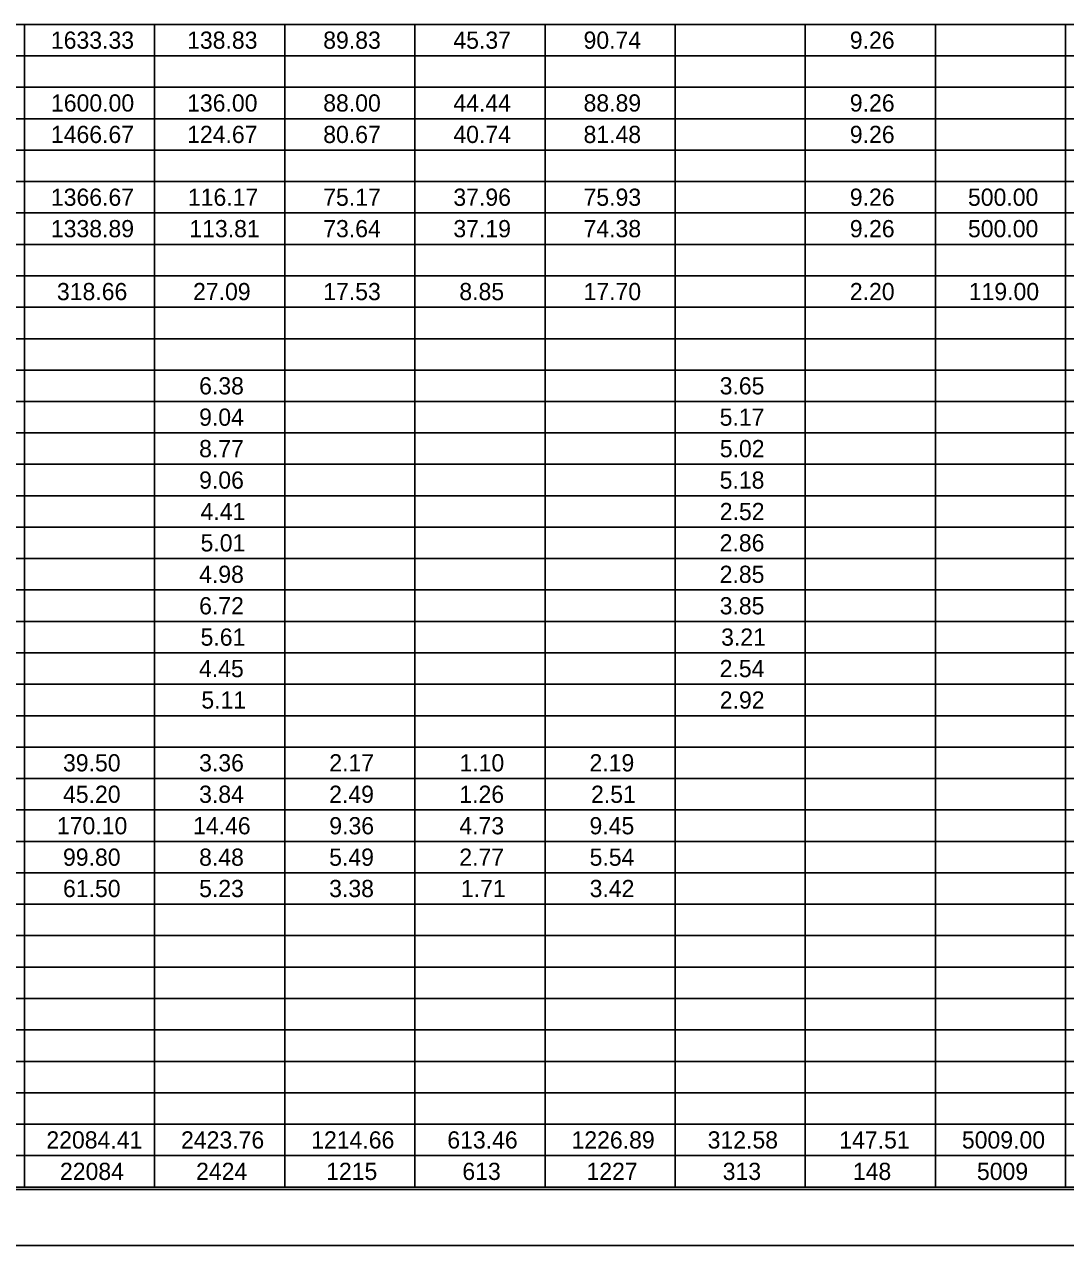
# Model space of a CAD drawing. Extents: x 0 to 34, y 0 to 22.
# Drawn here: x 16.38 to 25.65, y 0 to 10.87 of the extents above; entities that cross this region are included whole.
import ezdxf

# ---------------------------------------------------------------- set-up
doc = ezdxf.new("R2010")
doc.units = 0
for name, color, linetype in [('SH_Border', 7, 'Continuous'), ('SH_Cut_Line', 7, 'Continuous'), ('SH_Text', 7, 'Continuous')]:
    doc.layers.add(name, color=color, linetype=linetype)

msp = doc.modelspace()

# ---------------------------------------------------------------- linework, layer by layer
at = {"layer": 'SH_Border'}
msp.add_lwpolyline([(1.5, 21.5), (33.5, 21.5), (33.5, 0.5), (1.5, 0.5)], close=True, dxfattribs=at)
at = {"layer": 'SH_Cut_Line'}
msp.add_lwpolyline([(0, 0), (34, 0), (34, 22), (0, 22)], close=True, dxfattribs=at)
at = {"layer": 'SH_Text'}
for p, q in [((15.22, 10.871), (16.378, 10.871)), ((16.378, 10.871), (24.49, 10.871)), ((16.378, 10.871), (16.378, 10.591)), ((17.537, 10.871), (17.537, 10.591)), ((18.696, 10.871), (18.696, 10.591)), ((19.855, 10.871), (19.855, 10.591)), ((21.014, 10.871), (21.014, 10.591)), ((22.173, 10.871), (22.173, 10.591)), ((23.331, 10.871), (23.331, 10.591)), ((24.49, 10.871), (25.649, 10.871)), ((24.49, 10.871), (24.49, 10.591)), ((25.649, 10.871), (27.967, 10.871)), ((25.649, 10.871), (25.649, 10.591)), ((15.22, 10.591), (16.378, 10.591)), ((16.378, 10.591), (24.49, 10.591)), ((16.378, 10.591), (16.378, 10.311)), ((17.537, 10.591), (17.537, 10.311)), ((18.696, 10.591), (18.696, 10.311)), ((19.855, 10.591), (19.855, 10.311)), ((21.014, 10.591), (21.014, 10.311)), ((22.173, 10.591), (22.173, 10.311)), ((23.331, 10.591), (23.331, 10.311)), ((24.49, 10.591), (25.649, 10.591)), ((24.49, 10.591), (24.49, 10.311)), ((25.649, 10.591), (27.967, 10.591)), ((25.649, 10.591), (25.649, 10.311)), ((15.22, 10.311), (16.378, 10.311)), ((16.378, 10.311), (24.49, 10.311)), ((16.378, 10.311), (16.378, 10.031)), ((17.537, 10.311), (17.537, 10.031)), ((18.696, 10.311), (18.696, 10.031)), ((19.855, 10.311), (19.855, 10.031)), ((21.014, 10.311), (21.014, 10.031)), ((22.173, 10.311), (22.173, 10.031)), ((23.331, 10.311), (23.331, 10.031)), ((24.49, 10.311), (25.649, 10.311)), ((24.49, 10.311), (24.49, 10.031)), ((25.649, 10.311), (27.967, 10.311)), ((25.649, 10.311), (25.649, 10.031)), ((15.22, 10.031), (16.378, 10.031)), ((16.378, 10.031), (24.49, 10.031)), ((16.378, 10.031), (16.378, 9.752)), ((17.537, 10.031), (17.537, 9.752)), ((18.696, 10.031), (18.696, 9.752)), ((19.855, 10.031), (19.855, 9.752)), ((21.014, 10.031), (21.014, 9.752)), ((22.173, 10.031), (22.173, 9.752)), ((23.331, 10.031), (23.331, 9.752)), ((24.49, 10.031), (25.649, 10.031)), ((24.49, 10.031), (24.49, 9.752)), ((25.649, 10.031), (27.967, 10.031)), ((25.649, 10.031), (25.649, 9.752)), ((15.22, 9.752), (16.378, 9.752)), ((16.378, 9.752), (24.49, 9.752)), ((16.378, 9.752), (16.378, 9.472)), ((17.537, 9.752), (17.537, 9.472)), ((18.696, 9.752), (18.696, 9.472)), ((19.855, 9.752), (19.855, 9.472)), ((21.014, 9.752), (21.014, 9.472)), ((22.173, 9.752), (22.173, 9.472)), ((23.331, 9.752), (23.331, 9.472)), ((24.49, 9.752), (25.649, 9.752)), ((24.49, 9.752), (24.49, 9.472)), ((25.649, 9.752), (27.967, 9.752)), ((25.649, 9.752), (25.649, 9.472)), ((15.22, 9.472), (16.378, 9.472)), ((16.378, 9.472), (24.49, 9.472)), ((16.378, 9.472), (16.378, 9.192)), ((17.537, 9.472), (17.537, 9.192)), ((18.696, 9.472), (18.696, 9.192)), ((19.855, 9.472), (19.855, 9.192)), ((21.014, 9.472), (21.014, 9.192)), ((22.173, 9.472), (22.173, 9.192)), ((23.331, 9.472), (23.331, 9.192)), ((24.49, 9.472), (25.649, 9.472)), ((24.49, 9.472), (24.49, 9.192)), ((25.649, 9.472), (27.967, 9.472)), ((25.649, 9.472), (25.649, 9.192)), ((15.22, 9.192), (16.378, 9.192)), ((16.378, 9.192), (24.49, 9.192)), ((16.378, 9.192), (16.378, 8.913)), ((17.537, 9.192), (17.537, 8.913)), ((18.696, 9.192), (18.696, 8.913)), ((19.855, 9.192), (19.855, 8.913)), ((21.014, 9.192), (21.014, 8.913)), ((22.173, 9.192), (22.173, 8.913)), ((23.331, 9.192), (23.331, 8.913)), ((24.49, 9.192), (25.649, 9.192)), ((24.49, 9.192), (24.49, 8.913)), ((25.649, 9.192), (27.967, 9.192)), ((25.649, 9.192), (25.649, 8.913)), ((15.22, 8.913), (16.378, 8.913)), ((16.378, 8.913), (24.49, 8.913)), ((16.378, 8.913), (16.378, 8.633)), ((17.537, 8.913), (17.537, 8.633)), ((18.696, 8.913), (18.696, 8.633)), ((19.855, 8.913), (19.855, 8.633)), ((21.014, 8.913), (21.014, 8.633)), ((22.173, 8.913), (22.173, 8.633)), ((23.331, 8.913), (23.331, 8.633)), ((24.49, 8.913), (25.649, 8.913)), ((24.49, 8.913), (24.49, 8.633)), ((25.649, 8.913), (27.967, 8.913)), ((25.649, 8.913), (25.649, 8.633)), ((15.22, 8.633), (16.378, 8.633)), ((16.378, 8.633), (24.49, 8.633)), ((16.378, 8.633), (16.378, 8.353)), ((17.537, 8.633), (17.537, 8.353)), ((18.696, 8.633), (18.696, 8.353)), ((19.855, 8.633), (19.855, 8.353)), ((21.014, 8.633), (21.014, 8.353)), ((22.173, 8.633), (22.173, 8.353)), ((23.331, 8.633), (23.331, 8.353)), ((24.49, 8.633), (25.649, 8.633)), ((24.49, 8.633), (24.49, 8.353)), ((25.649, 8.633), (27.967, 8.633)), ((25.649, 8.633), (25.649, 8.353)), ((15.22, 8.353), (16.378, 8.353)), ((16.378, 8.353), (24.49, 8.353)), ((16.378, 8.353), (16.378, 8.073)), ((17.537, 8.353), (17.537, 8.073)), ((18.696, 8.353), (18.696, 8.073)), ((19.855, 8.353), (19.855, 8.073)), ((21.014, 8.353), (21.014, 8.073)), ((22.173, 8.353), (22.173, 8.073)), ((23.331, 8.353), (23.331, 8.073)), ((24.49, 8.353), (25.649, 8.353)), ((24.49, 8.353), (24.49, 8.073)), ((25.649, 8.353), (27.967, 8.353)), ((25.649, 8.353), (25.649, 8.073)), ((15.22, 8.073), (16.378, 8.073)), ((16.378, 8.073), (24.49, 8.073)), ((16.378, 8.073), (16.378, 7.794)), ((17.537, 8.073), (17.537, 7.794)), ((18.696, 8.073), (18.696, 7.794)), ((19.855, 8.073), (19.855, 7.794)), ((21.014, 8.073), (21.014, 7.794)), ((22.173, 8.073), (22.173, 7.794)), ((23.331, 8.073), (23.331, 7.794)), ((24.49, 8.073), (25.649, 8.073)), ((24.49, 8.073), (24.49, 7.794)), ((25.649, 8.073), (27.967, 8.073)), ((25.649, 8.073), (25.649, 7.794)), ((15.22, 7.794), (16.378, 7.794)), ((16.378, 7.794), (24.49, 7.794)), ((16.378, 7.794), (16.378, 7.514)), ((17.537, 7.794), (17.537, 7.514)), ((18.696, 7.794), (18.696, 7.514)), ((19.855, 7.794), (19.855, 7.514)), ((21.014, 7.794), (21.014, 7.514)), ((22.173, 7.794), (22.173, 7.514)), ((23.331, 7.794), (23.331, 7.514)), ((24.49, 7.794), (25.649, 7.794)), ((24.49, 7.794), (24.49, 7.514)), ((25.649, 7.794), (27.967, 7.794)), ((25.649, 7.794), (25.649, 7.514)), ((15.22, 7.514), (16.378, 7.514)), ((16.378, 7.514), (24.49, 7.514)), ((16.378, 7.514), (16.378, 7.234)), ((17.537, 7.514), (17.537, 7.234)), ((18.696, 7.514), (18.696, 7.234)), ((19.855, 7.514), (19.855, 7.234)), ((21.014, 7.514), (21.014, 7.234)), ((22.173, 7.514), (22.173, 7.234)), ((23.331, 7.514), (23.331, 7.234)), ((24.49, 7.514), (25.649, 7.514)), ((24.49, 7.514), (24.49, 7.234)), ((25.649, 7.514), (27.967, 7.514)), ((25.649, 7.514), (25.649, 7.234)), ((15.22, 7.234), (16.378, 7.234)), ((16.378, 7.234), (24.49, 7.234)), ((16.378, 7.234), (16.378, 6.955)), ((17.537, 7.234), (17.537, 6.955)), ((18.696, 7.234), (18.696, 6.955)), ((19.855, 7.234), (19.855, 6.955)), ((21.014, 7.234), (21.014, 6.955)), ((22.173, 7.234), (22.173, 6.955)), ((23.331, 7.234), (23.331, 6.955)), ((24.49, 7.234), (25.649, 7.234)), ((24.49, 7.234), (24.49, 6.955)), ((25.649, 7.234), (27.967, 7.234)), ((25.649, 7.234), (25.649, 6.955)), ((15.22, 6.955), (16.378, 6.955)), ((16.378, 6.955), (24.49, 6.955)), ((16.378, 6.955), (16.378, 6.675)), ((17.537, 6.955), (17.537, 6.675)), ((18.696, 6.955), (18.696, 6.675)), ((19.855, 6.955), (19.855, 6.675)), ((21.014, 6.955), (21.014, 6.675)), ((22.173, 6.955), (22.173, 6.675)), ((23.331, 6.955), (23.331, 6.675)), ((24.49, 6.955), (25.649, 6.955)), ((24.49, 6.955), (24.49, 6.675)), ((25.649, 6.955), (27.967, 6.955)), ((25.649, 6.955), (25.649, 6.675)), ((15.22, 6.675), (16.378, 6.675)), ((16.378, 6.675), (24.49, 6.675)), ((16.378, 6.675), (16.378, 6.395)), ((17.537, 6.675), (17.537, 6.395)), ((18.696, 6.675), (18.696, 6.395)), ((19.855, 6.675), (19.855, 6.395)), ((21.014, 6.675), (21.014, 6.395)), ((22.173, 6.675), (22.173, 6.395)), ((23.331, 6.675), (23.331, 6.395)), ((24.49, 6.675), (25.649, 6.675)), ((24.49, 6.675), (24.49, 6.395)), ((25.649, 6.675), (27.967, 6.675)), ((25.649, 6.675), (25.649, 6.395)), ((15.22, 6.395), (16.378, 6.395)), ((16.378, 6.395), (24.49, 6.395)), ((16.378, 6.395), (16.378, 6.115)), ((17.537, 6.395), (17.537, 6.115)), ((18.696, 6.395), (18.696, 6.115)), ((19.855, 6.395), (19.855, 6.115)), ((21.014, 6.395), (21.014, 6.115)), ((22.173, 6.395), (22.173, 6.115)), ((23.331, 6.395), (23.331, 6.115)), ((24.49, 6.395), (25.649, 6.395)), ((24.49, 6.395), (24.49, 6.115)), ((25.649, 6.395), (27.967, 6.395)), ((25.649, 6.395), (25.649, 6.115)), ((15.22, 6.115), (16.378, 6.115)), ((16.378, 6.115), (24.49, 6.115)), ((16.378, 6.115), (16.378, 5.836)), ((17.537, 6.115), (17.537, 5.836)), ((18.696, 6.115), (18.696, 5.836)), ((19.855, 6.115), (19.855, 5.836)), ((21.014, 6.115), (21.014, 5.836)), ((22.173, 6.115), (22.173, 5.836)), ((23.331, 6.115), (23.331, 5.836)), ((24.49, 6.115), (25.649, 6.115)), ((24.49, 6.115), (24.49, 5.836)), ((25.649, 6.115), (27.967, 6.115)), ((25.649, 6.115), (25.649, 5.836)), ((15.22, 5.836), (16.378, 5.836)), ((16.378, 5.836), (24.49, 5.836)), ((16.378, 5.836), (16.378, 5.276)), ((17.537, 5.836), (17.537, 5.276)), ((18.696, 5.836), (18.696, 5.276)), ((19.855, 5.836), (19.855, 5.276)), ((21.014, 5.836), (21.014, 5.276)), ((22.173, 5.836), (22.173, 5.276)), ((23.331, 5.836), (23.331, 5.276)), ((24.49, 5.836), (25.649, 5.836)), ((24.49, 5.836), (24.49, 5.276)), ((25.649, 5.836), (27.967, 5.836)), ((25.649, 5.836), (25.649, 5.276)), ((15.22, 5.556), (16.378, 5.556)), ((16.378, 5.556), (24.49, 5.556)), ((24.49, 5.556), (25.649, 5.556)), ((25.649, 5.556), (27.967, 5.556)), ((15.22, 5.276), (16.378, 5.276)), ((16.378, 5.276), (24.49, 5.276)), ((16.378, 5.276), (16.378, 4.997)), ((17.537, 5.276), (17.537, 4.997)), ((18.696, 5.276), (18.696, 4.997)), ((19.855, 5.276), (19.855, 4.997)), ((21.014, 5.276), (21.014, 4.997)), ((22.173, 5.276), (22.173, 4.997)), ((23.331, 5.276), (23.331, 4.997)), ((24.49, 5.276), (25.649, 5.276)), ((24.49, 5.276), (24.49, 4.997)), ((25.649, 5.276), (27.967, 5.276)), ((25.649, 5.276), (25.649, 4.997)), ((15.22, 4.997), (16.378, 4.997)), ((16.378, 4.997), (24.49, 4.997)), ((16.378, 4.997), (16.378, 4.717)), ((17.537, 4.997), (17.537, 4.717)), ((18.696, 4.997), (18.696, 4.717)), ((19.855, 4.997), (19.855, 4.717)), ((21.014, 4.997), (21.014, 4.717)), ((22.173, 4.997), (22.173, 4.717)), ((23.331, 4.997), (23.331, 4.717)), ((24.49, 4.997), (25.649, 4.997)), ((24.49, 4.997), (24.49, 4.717)), ((25.649, 4.997), (27.967, 4.997)), ((25.649, 4.997), (25.649, 4.717)), ((15.22, 4.717), (16.378, 4.717)), ((16.378, 4.717), (24.49, 4.717)), ((16.378, 4.717), (16.378, 4.437)), ((17.537, 4.717), (17.537, 4.437)), ((18.696, 4.717), (18.696, 4.437)), ((19.855, 4.717), (19.855, 4.437)), ((21.014, 4.717), (21.014, 4.437)), ((22.173, 4.717), (22.173, 4.437)), ((23.331, 4.717), (23.331, 4.437)), ((24.49, 4.717), (25.649, 4.717)), ((24.49, 4.717), (24.49, 4.437)), ((25.649, 4.717), (27.967, 4.717)), ((25.649, 4.717), (25.649, 4.437)), ((15.22, 4.437), (16.378, 4.437)), ((16.378, 4.437), (24.49, 4.437)), ((16.378, 4.437), (16.378, 3.878)), ((17.537, 4.437), (17.537, 3.878)), ((18.696, 4.437), (18.696, 3.878)), ((19.855, 4.437), (19.855, 3.878)), ((21.014, 4.437), (21.014, 3.878)), ((22.173, 4.437), (22.173, 3.878)), ((23.331, 4.437), (23.331, 3.878)), ((24.49, 4.437), (25.649, 4.437)), ((24.49, 4.437), (24.49, 3.878)), ((25.649, 4.437), (27.967, 4.437)), ((25.649, 4.437), (25.649, 3.878)), ((15.22, 4.157), (16.378, 4.157)), ((16.378, 4.157), (24.49, 4.157)), ((24.49, 4.157), (25.649, 4.157)), ((25.649, 4.157), (27.967, 4.157)), ((15.22, 3.878), (16.378, 3.878)), ((16.378, 3.878), (24.49, 3.878)), ((16.378, 3.878), (16.378, 3.598)), ((17.537, 3.878), (17.537, 3.598)), ((18.696, 3.878), (18.696, 3.598)), ((19.855, 3.878), (19.855, 3.598)), ((21.014, 3.878), (21.014, 3.598)), ((22.173, 3.878), (22.173, 3.598)), ((23.331, 3.878), (23.331, 3.598)), ((24.49, 3.878), (25.649, 3.878)), ((24.49, 3.878), (24.49, 3.598)), ((25.649, 3.878), (27.967, 3.878)), ((25.649, 3.878), (25.649, 3.598)), ((15.22, 3.598), (16.378, 3.598)), ((16.378, 3.598), (24.49, 3.598)), ((16.378, 3.598), (16.378, 3.318)), ((17.537, 3.598), (17.537, 3.318)), ((18.696, 3.598), (18.696, 3.318)), ((19.855, 3.598), (19.855, 3.318)), ((21.014, 3.598), (21.014, 3.318)), ((22.173, 3.598), (22.173, 3.318)), ((23.331, 3.598), (23.331, 3.318)), ((24.49, 3.598), (25.649, 3.598)), ((24.49, 3.598), (24.49, 3.318)), ((25.649, 3.598), (27.967, 3.598)), ((25.649, 3.598), (25.649, 3.318)), ((15.22, 3.318), (16.378, 3.318)), ((16.378, 3.318), (24.49, 3.318)), ((16.378, 3.318), (16.378, 3.038)), ((17.537, 3.318), (17.537, 3.038)), ((18.696, 3.318), (18.696, 3.038)), ((19.855, 3.318), (19.855, 3.038)), ((21.014, 3.318), (21.014, 3.038)), ((22.173, 3.318), (22.173, 3.038)), ((23.331, 3.318), (23.331, 3.038)), ((24.49, 3.318), (25.649, 3.318)), ((24.49, 3.318), (24.49, 3.038)), ((25.649, 3.318), (27.967, 3.318)), ((25.649, 3.318), (25.649, 3.038)), ((15.22, 3.038), (16.378, 3.038)), ((16.378, 3.038), (24.49, 3.038)), ((16.378, 3.038), (16.378, 2.479)), ((17.537, 3.038), (17.537, 2.479)), ((18.696, 3.038), (18.696, 2.479)), ((19.855, 3.038), (19.855, 2.479)), ((21.014, 3.038), (21.014, 2.479)), ((22.173, 3.038), (22.173, 2.479)), ((23.331, 3.038), (23.331, 2.479)), ((24.49, 3.038), (25.649, 3.038)), ((24.49, 3.038), (24.49, 2.479)), ((25.649, 3.038), (27.967, 3.038)), ((25.649, 3.038), (25.649, 2.479)), ((15.22, 2.759), (16.378, 2.759)), ((16.378, 2.759), (24.49, 2.759)), ((24.49, 2.759), (25.649, 2.759)), ((25.649, 2.759), (27.967, 2.759)), ((15.22, 2.479), (16.378, 2.479)), ((16.378, 2.479), (24.49, 2.479)), ((16.378, 2.479), (16.378, 2.199)), ((17.537, 2.479), (17.537, 2.199)), ((18.696, 2.479), (18.696, 2.199)), ((19.855, 2.479), (19.855, 2.199)), ((21.014, 2.479), (21.014, 2.199)), ((22.173, 2.479), (22.173, 2.199)), ((23.331, 2.479), (23.331, 2.199)), ((24.49, 2.479), (25.649, 2.479)), ((24.49, 2.479), (24.49, 2.199)), ((25.649, 2.479), (27.967, 2.479)), ((25.649, 2.479), (25.649, 2.199)), ((15.22, 2.199), (16.378, 2.199)), ((16.378, 2.199), (24.49, 2.199)), ((16.378, 2.199), (16.378, 1.92)), ((17.537, 2.199), (17.537, 1.92)), ((18.696, 2.199), (18.696, 1.92)), ((19.855, 2.199), (19.855, 1.92)), ((21.014, 2.199), (21.014, 1.92)), ((22.173, 2.199), (22.173, 1.92)), ((23.331, 2.199), (23.331, 1.92)), ((24.49, 2.199), (25.649, 2.199)), ((24.49, 2.199), (24.49, 1.92)), ((25.649, 2.199), (27.967, 2.199)), ((25.649, 2.199), (25.649, 1.92)), ((15.22, 1.92), (16.378, 1.92)), ((16.378, 1.92), (24.49, 1.92)), ((16.378, 1.92), (16.378, 1.64)), ((17.537, 1.92), (17.537, 1.64)), ((18.696, 1.92), (18.696, 1.64)), ((19.855, 1.92), (19.855, 1.64)), ((21.014, 1.92), (21.014, 1.64)), ((22.173, 1.92), (22.173, 1.64)), ((23.331, 1.92), (23.331, 1.64)), ((24.49, 1.92), (25.649, 1.92)), ((24.49, 1.92), (24.49, 1.64)), ((25.649, 1.92), (27.967, 1.92)), ((25.649, 1.92), (25.649, 1.64)), ((15.22, 1.64), (16.378, 1.64)), ((16.378, 1.64), (24.49, 1.64)), ((16.378, 1.64), (16.378, 1.08)), ((17.537, 1.64), (17.537, 1.08)), ((18.696, 1.64), (18.696, 1.08)), ((19.855, 1.64), (19.855, 1.08)), ((21.014, 1.64), (21.014, 1.08)), ((22.173, 1.64), (22.173, 1.08)), ((23.331, 1.64), (23.331, 1.08)), ((24.49, 1.64), (25.649, 1.64)), ((24.49, 1.64), (24.49, 1.08)), ((25.649, 1.64), (27.967, 1.64)), ((25.649, 1.64), (25.649, 1.08)), ((15.22, 1.36), (16.378, 1.36)), ((16.378, 1.36), (24.49, 1.36)), ((24.49, 1.36), (25.649, 1.36)), ((25.649, 1.36), (27.967, 1.36)), ((15.22, 1.08), (16.378, 1.08)), ((16.378, 1.08), (24.49, 1.08)), ((16.378, 1.08), (16.378, 0.801)), ((17.537, 1.08), (17.537, 0.801)), ((18.696, 1.08), (18.696, 0.801)), ((19.855, 1.08), (19.855, 0.801)), ((21.014, 1.08), (21.014, 0.801)), ((22.173, 1.08), (22.173, 0.801)), ((23.331, 1.08), (23.331, 0.801)), ((24.49, 1.08), (25.649, 1.08)), ((24.49, 1.08), (24.49, 0.801)), ((25.649, 1.08), (27.967, 1.08)), ((25.649, 1.08), (25.649, 0.801)), ((15.22, 0.801), (16.378, 0.801)), ((16.378, 0.801), (24.49, 0.801)), ((16.378, 0.801), (16.378, 0.521)), ((17.537, 0.801), (17.537, 0.521)), ((18.696, 0.801), (18.696, 0.521)), ((19.855, 0.801), (19.855, 0.521)), ((21.014, 0.801), (21.014, 0.521)), ((22.173, 0.801), (22.173, 0.521)), ((23.331, 0.801), (23.331, 0.521)), ((24.49, 0.801), (25.649, 0.801)), ((24.49, 0.801), (24.49, 0.521)), ((25.649, 0.801), (27.967, 0.801)), ((25.649, 0.801), (25.649, 0.521)), ((15.22, 0.521), (16.378, 0.521)), ((16.378, 0.521), (24.49, 0.521)), ((24.49, 0.521), (25.649, 0.521)), ((25.649, 0.521), (27.967, 0.521))]:
    msp.add_line(p, q, dxfattribs=at)

# ---------------------------------------------------------------- texts
for s, p in [('1633.33', (16.614, 10.654)), ('138.83', (17.827, 10.654)), ('89.83', (19.039, 10.654)), ('45.37', (20.198, 10.654)), ('90.74', (21.357, 10.654)), ('9.26', (23.728, 10.654)), ('1600.00', (16.615, 10.095)), ('136.00', (17.827, 10.095)), ('88.00', (19.039, 10.095)), ('44.44', (20.198, 10.095)), ('88.89', (21.357, 10.095)), ('9.26', (23.728, 10.095)), ('1466.67', (16.614, 9.815)), ('124.67', (17.827, 9.815)), ('80.67', (19.039, 9.815)), ('40.74', (20.198, 9.815)), ('81.48', (21.357, 9.815)), ('9.26', (23.728, 9.815)), ('1366.67', (16.614, 9.256)), ('116.17', (17.834, 9.256)), ('75.17', (19.039, 9.256)), ('37.96', (20.198, 9.256)), ('75.93', (21.357, 9.256)), ('9.26', (23.728, 9.256)), ('500.00', (24.78, 9.256)), ('1338.89', (16.614, 8.976)), ('113.81', (17.847, 8.976)), ('73.64', (19.039, 8.976)), ('37.19', (20.198, 8.976)), ('74.38', (21.357, 8.976)), ('9.26', (23.728, 8.976)), ('500.00', (24.78, 8.976)), ('318.66', (16.668, 8.416)), ('27.09', (17.88, 8.416)), ('17.53', (19.039, 8.416)), ('8.85', (20.251, 8.416)), ('17.70', (21.357, 8.416)), ('2.20', (23.728, 8.416)), ('119.00', (24.787, 8.416)), ('6.38', (17.934, 7.577)), ('3.65', (22.569, 7.577)), ('9.04', (17.934, 7.298)), ('5.17', (22.569, 7.298)), ('8.77', (17.934, 7.018)), ('5.02', (22.57, 7.018)), ('9.06', (17.934, 6.738)), ('5.18', (22.569, 6.738)), ('4.41', (17.947, 6.458)), ('2.52', (22.57, 6.458)), ('5.01', (17.947, 6.179)), ('2.86', (22.569, 6.179)), ('4.98', (17.934, 5.899)), ('2.85', (22.569, 5.899)), ('6.72', (17.934, 5.619)), ('3.85', (22.569, 5.619)), ('5.61', (17.947, 5.34)), ('3.21', (22.582, 5.34)), ('4.45', (17.933, 5.06)), ('2.54', (22.569, 5.06)), ('5.11', (17.954, 4.78)), ('2.92', (22.57, 4.78)), ('39.50', (16.722, 4.221)), ('3.36', (17.934, 4.221)), ('2.17', (19.093, 4.221)), ('1.10', (20.252, 4.221)), ('2.19', (21.41, 4.221)), ('45.20', (16.722, 3.941)), ('3.84', (17.934, 3.941)), ('2.49', (19.092, 3.941)), ('1.26', (20.251, 3.941)), ('2.51', (21.424, 3.941)), ('170.10', (16.668, 3.661)), ('14.46', (17.88, 3.661)), ('9.36', (19.093, 3.661)), ('4.73', (20.251, 3.661)), ('9.45', (21.41, 3.661)), ('99.80', (16.722, 3.381)), ('8.48', (17.934, 3.381)), ('5.49', (19.092, 3.381)), ('2.77', (20.251, 3.381)), ('5.54', (21.411, 3.381)), ('61.50', (16.722, 3.102)), ('5.23', (17.934, 3.102)), ('3.38', (19.092, 3.102)), ('1.71', (20.265, 3.102)), ('3.42', (21.411, 3.102)), ('22084.41', (16.574, 0.864)), ('2423.76', (17.773, 0.864)), ('1214.66', (18.932, 0.864)), ('613.46', (20.144, 0.864)), ('1226.89', (21.25, 0.864)), ('312.58', (22.462, 0.864)), ('147.51', (23.634, 0.864)), ('5009.00', (24.726, 0.864)), ('22084', (16.695, 0.584)), ('2424', (17.907, 0.584)), ('1215', (19.065, 0.584)), ('613', (20.278, 0.584)), ('1227', (21.383, 0.584)), ('313', (22.596, 0.584)), ('148', (23.755, 0.584)), ('5009', (24.86, 0.584))]:
    msp.add_text(s, height=0.1532, dxfattribs=at).set_placement(p)

doc.saveas('drawing.dxf')
